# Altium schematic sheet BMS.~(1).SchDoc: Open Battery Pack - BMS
size A3; Date: 26/03/2019; Author: Morgane Vallée - Samuel Lesueur; Revision: 1.0; SheetNumber: 1; SheetTotal: 3
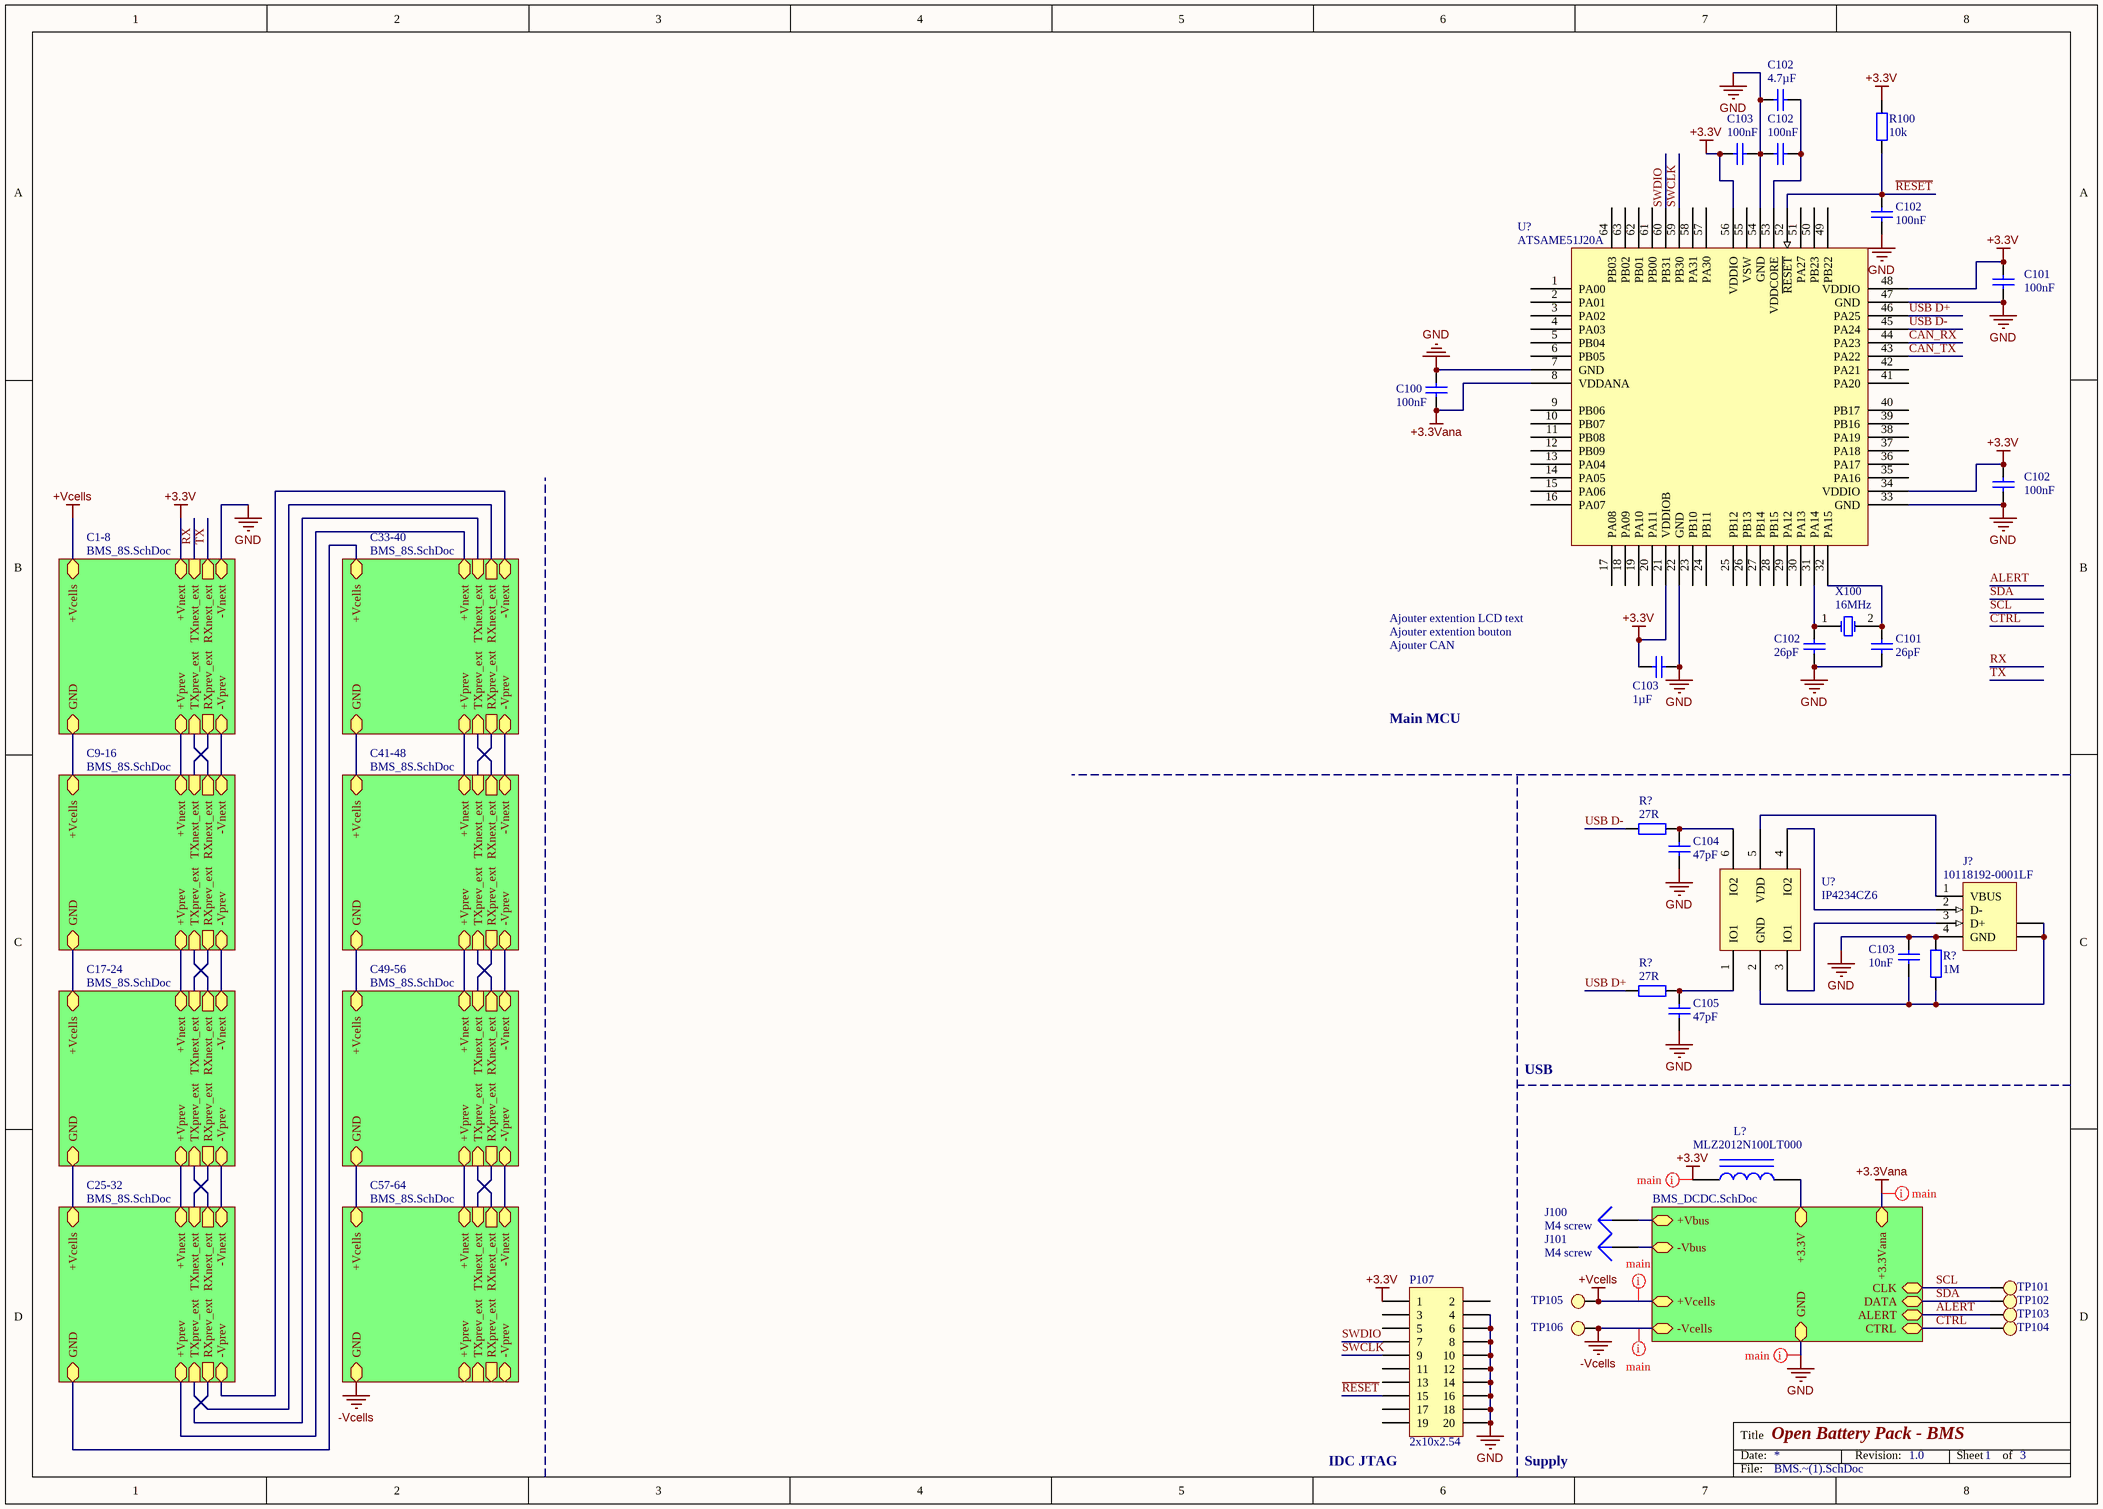
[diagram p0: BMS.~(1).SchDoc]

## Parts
(Parts that share a designator on the sheet are numbered #1, #2 ... from top to bottom, then left to right.)
C100  100nF  [C0603]
C101#1  100nF  [C0603]
C101#2  26pF  [C0603]
C102#1  4.7µF  [C0603]
C102#2  100nF  [C0603]
C102#3  100nF  [C0603]
C102#4  100nF  [C0603]
C102#5  26pF  [C0603]
C103#1  100nF  [C0603]
C103#2  1µF  [C0603]
C103#3  10nF  [C0603]
C104  47pF  [C0603]
C105  47pF  [C0603]
J100  M4 screw  [HOLE_4]
J101  M4 screw  [HOLE_4]
J?  10118192-0001LF  [353576]
L?  MLZ2012N100LT000  [C0805]
P107  2x10x2.54  [HDR2X10]
R100  10k  [R0603]
R?#1  27R  [R0603]
R?#2  1M  [R0603]
R?#3  27R  [R0603]
TP101  Test Point  [Test Point]  (value not drawn)
TP102  Test Point  [Test Point]  (value not drawn)
TP103  Test Point  [Test Point]  (value not drawn)
TP104  Test Point  [Test Point]  (value not drawn)
TP105  Test Point  [Test Point]  (value not drawn)
TP106  Test Point  [Test Point]  (value not drawn)
U?#1  ATSAME51J20A  [TQFP-64N]
U?#2  IP4234CZ6  [VISHAY TSOP-6 MO-193C]
X100  16MHz  [ABRACON ABLS]

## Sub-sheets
C1-8 = BMS_8S.SchDoc: +Vcells, GND, -Vprev, RXnext_ext (out), +Vnext, -Vnext, TXnext_ext (in), RXprev_ext (out), +Vprev, TXprev_ext (in)
C9-16 = BMS_8S.SchDoc: +Vcells, GND, -Vprev, RXnext_ext (out), +Vnext, -Vnext, TXnext_ext (in), RXprev_ext (out), +Vprev, TXprev_ext (in)
C17-24 = BMS_8S.SchDoc: +Vcells, GND, -Vprev, RXnext_ext (out), +Vnext, -Vnext, TXnext_ext (in), RXprev_ext (out), +Vprev, TXprev_ext (in)
C25-32 = BMS_8S.SchDoc: +Vcells, GND, -Vprev, RXnext_ext (out), +Vnext, -Vnext, TXnext_ext (in), RXprev_ext (out), +Vprev, TXprev_ext (in)
C33-40 = BMS_8S.SchDoc: +Vcells, GND, -Vprev, RXnext_ext (out), +Vnext, -Vnext, TXnext_ext (in), RXprev_ext (out), +Vprev, TXprev_ext (in)
C41-48 = BMS_8S.SchDoc: +Vcells, GND, -Vprev, RXnext_ext (out), +Vnext, -Vnext, TXnext_ext (in), RXprev_ext (out), +Vprev, TXprev_ext (in)
C49-56 = BMS_8S.SchDoc: +Vcells, GND, -Vprev, RXnext_ext (out), +Vnext, -Vnext, TXnext_ext (in), RXprev_ext (out), +Vprev, TXprev_ext (in)
C57-64 = BMS_8S.SchDoc: +Vcells, GND, -Vprev, RXnext_ext (out), +Vnext, -Vnext, TXnext_ext (in), RXprev_ext (out), +Vprev, TXprev_ext (in)
? = BMS_DCDC.SchDoc: CTRL (bidir), CLK (bidir), DATA (bidir), ALERT (bidir), GND, +3.3V, -Vbus, +Vbus, -Vcells, +Vcells, +3.3Vana

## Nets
+3.3V: C101#1.2 C102#4.2 C103#1.2 C103#2.2 L?.1 P107.1 R100.2 U?#1.21(VDDIOB) U?#1.34(VDDIO) U?#1.48(VDDIO) U?#1.56(VDDIO) ; sheet C1-8/+Vnext
+3.3Vana: C100.1 U?#1.8(VDDANA) ; sheet /+3.3Vana
+Vcells: TP105.1 ; sheet /+Vcells, sheet C1-8/+Vcells
-Vcells: TP106.1 ; sheet /-Vcells, sheet C57-64/GND
GND: C100.2 C101#1.1 C101#2.1 C102#1.2 C102#2.2 C102#3.1 C102#4.1 C102#5.1 C103#1.1 C103#2.1 C103#3.2 C104.1 C105.1 J?.4(GND) P107.4 P107.6 P107.8 P107.10 P107.12 P107.14 P107.16 P107.18 P107.20 R?#2.1 U?#1.7(GND) U?#1.22(GND) U?#1.33(GND) U?#1.47(GND) U?#1.54(GND) ; sheet /GND, sheet C1-8/-Vnext
ALERT: TP103.1 ; sheet /ALERT
CAN_RX: U?#1.44(PA23)
CAN_TX: U?#1.43(PA22)
CTRL: TP104.1 ; sheet /CTRL
~{RESET}: C102#3.2 P107.15 R100.1 U?#1.52(~{RESET})
SCL: TP101.1 ; sheet /CLK
SDA: TP102.1 ; sheet /DATA
SWCLK: P107.9 U?#1.59(PB30)
SWDIO: P107.7 U?#1.60(PB31)
USB D+: R?#3.1 U?#1.46(PA25)
USB D-: R?#1.1 U?#1.45(PA24)
NetC101#2_2: C101#2.2 U?#1.32(PA15) X100.2(OSC2)
NetC102#1_1: C102#1.1 C102#2.1 U?#1.53(VDDCORE)
NetC102#5_2: C102#5.2 U?#1.31(PA14) X100.1(OSC1)
NetC103#3_1: C103#3.1 J?.5(SHLD) J?.6(SHLD) R?#2.2 U?#2.2(GND)
NetC104_2: C104.2 R?#1.2 U?#2.6(IO2)
NetC105_2: C105.2 R?#3.2 U?#2.1(IO1)
NetJ100_1: J100.1 ; sheet /+Vbus
NetJ101_1: J101.1 ; sheet /-Vbus
NetJ?_1: J?.1(VBUS) U?#2.5(VDD)
NetJ?_2: J?.2(D-) U?#2.4(IO2)
NetJ?_3: J?.3(D+) U?#2.3(IO1)
NetL?_2: L?.2 ; sheet /+3.3V
(unnamed): sheet C1-8/GND, sheet C9-16/+Vcells
(unnamed): sheet C1-8/-Vprev, sheet C9-16/-Vnext  [a separate net that carries the same name]
(unnamed): sheet C1-8/RXprev_ext, sheet C9-16/TXnext_ext  [a separate net that carries the same name]
(unnamed): sheet C1-8/+Vprev, sheet C9-16/+Vnext  [a separate net that carries the same name]
(unnamed): sheet C1-8/TXprev_ext, sheet C9-16/RXnext_ext  [a separate net that carries the same name]
(unnamed): sheet C9-16/GND, sheet C17-24/+Vcells  [a separate net that carries the same name]
(unnamed): sheet C9-16/-Vprev, sheet C17-24/-Vnext  [a separate net that carries the same name]
(unnamed): sheet C9-16/RXprev_ext, sheet C17-24/TXnext_ext  [a separate net that carries the same name]
(unnamed): sheet C9-16/+Vprev, sheet C17-24/+Vnext  [a separate net that carries the same name]
(unnamed): sheet C9-16/TXprev_ext, sheet C17-24/RXnext_ext  [a separate net that carries the same name]
(unnamed): sheet C17-24/GND, sheet C25-32/+Vcells  [a separate net that carries the same name]
(unnamed): sheet C17-24/-Vprev, sheet C25-32/-Vnext  [a separate net that carries the same name]
(unnamed): sheet C17-24/RXprev_ext, sheet C25-32/TXnext_ext  [a separate net that carries the same name]
(unnamed): sheet C17-24/+Vprev, sheet C25-32/+Vnext  [a separate net that carries the same name]
(unnamed): sheet C17-24/TXprev_ext, sheet C25-32/RXnext_ext  [a separate net that carries the same name]
(unnamed): sheet C25-32/GND, sheet C33-40/+Vcells  [a separate net that carries the same name]
(unnamed): sheet C25-32/-Vprev, sheet C33-40/-Vnext  [a separate net that carries the same name]
(unnamed): sheet C25-32/RXprev_ext, sheet C33-40/TXnext_ext  [a separate net that carries the same name]
(unnamed): sheet C25-32/+Vprev, sheet C33-40/+Vnext  [a separate net that carries the same name]
(unnamed): sheet C25-32/TXprev_ext, sheet C33-40/RXnext_ext  [a separate net that carries the same name]
(unnamed): sheet C33-40/GND, sheet C41-48/+Vcells  [a separate net that carries the same name]
(unnamed): sheet C33-40/-Vprev, sheet C41-48/-Vnext  [a separate net that carries the same name]
(unnamed): sheet C33-40/RXprev_ext, sheet C41-48/TXnext_ext  [a separate net that carries the same name]
(unnamed): sheet C33-40/+Vprev, sheet C41-48/+Vnext  [a separate net that carries the same name]
(unnamed): sheet C33-40/TXprev_ext, sheet C41-48/RXnext_ext  [a separate net that carries the same name]
(unnamed): sheet C41-48/GND, sheet C49-56/+Vcells  [a separate net that carries the same name]
(unnamed): sheet C41-48/-Vprev, sheet C49-56/-Vnext  [a separate net that carries the same name]
(unnamed): sheet C41-48/RXprev_ext, sheet C49-56/TXnext_ext  [a separate net that carries the same name]
(unnamed): sheet C41-48/+Vprev, sheet C49-56/+Vnext  [a separate net that carries the same name]
(unnamed): sheet C41-48/TXprev_ext, sheet C49-56/RXnext_ext  [a separate net that carries the same name]
(unnamed): sheet C49-56/GND, sheet C57-64/+Vcells  [a separate net that carries the same name]
(unnamed): sheet C49-56/-Vprev, sheet C57-64/-Vnext  [a separate net that carries the same name]
(unnamed): sheet C49-56/RXprev_ext, sheet C57-64/TXnext_ext  [a separate net that carries the same name]
(unnamed): sheet C49-56/+Vprev, sheet C57-64/+Vnext  [a separate net that carries the same name]
(unnamed): sheet C49-56/TXprev_ext, sheet C57-64/RXnext_ext  [a separate net that carries the same name]

Not connected (* = marked no-connect by the designer): P107 2 3 5 11 13 17 19; U?#1 1(PA00) 2(PA01) 3(PA02) 4(PA03) 5(PB04) 6(PB05) 9(PB06) 10(PB07) 11(PB08) 12(PB09) 13(PA04) 14(PA05) 15(PA06) 16(PA07) 17(PA08) 18(PA09) 19(PA10) 20(PA11) 23(PB10) 24(PB11) 25(PB12) 26(PB13) 27(PB14) 28(PB15) 29(PA12) 30(PA13) 35(PA16) 36(PA17) 37(PA18) 38(PA19) 39(PB16) 40(PB17) 41(PA20) 42(PA21) 49(PB22) 50(PB23) 51(PA27) 55(VSW) 57(PA30) 58(PA31) 61(PB00) 62(PB01) 63(PB02) 64(PB03)

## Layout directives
mark named main: +3.3V, +3.3Vana, +Vcells, -Vcells, GND

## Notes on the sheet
- Ajouter extention LCD text
- Ajouter extention bouton
- Ajouter CAN
- Main MCU
- USB
- (near P107) IDC JTAG
- Supply

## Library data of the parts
C100 C101#1 C101#2 C102#1-C102#5 C103#1-C103#3 C104 C105 = Cap: Capacitor
J100 J101 = Plug
J? = 1-353576-1: USB 1.1, Right Angle, SMT, A Type, Receptacle, 4 Position, White
L? = Inductor Iron: Magnetic-Core Inductor
P107 = Header 10X2: Header, 10-Pin, Dual row
R100 R?#1-R?#3 = Res2: Resistor
U?#2 = IP4234CZ6: Single USB 2.0 ESD protection to IEC 61000-4-2 level 4
X100 = XTAL: Crystal Oscillator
